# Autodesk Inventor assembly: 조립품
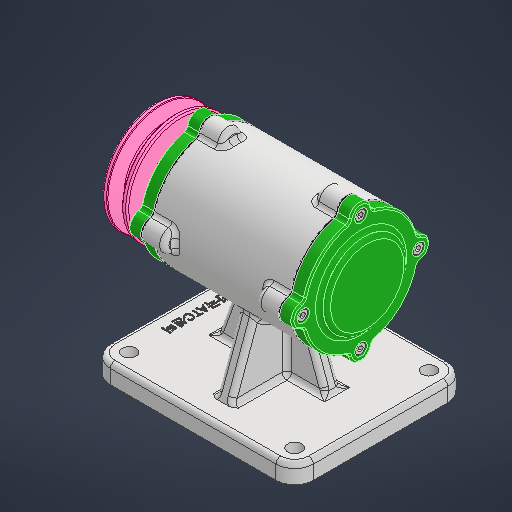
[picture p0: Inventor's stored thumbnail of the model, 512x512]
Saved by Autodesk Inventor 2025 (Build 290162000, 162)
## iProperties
Created: 2025-08
Part Number: 조립품
Document SubType Name: Assembly
Designer: infra006
Author: infra006
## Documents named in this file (12)
- C:\Users\infra006\Desktop\750806V1011\조립품.iam
- C:\Users\infra006\Desktop\750806V1011\부품eh.ipt
- C:\Users\infra006\Desktop\시험5\공용부품_20250517_2 (3)\앞커버\앞커버.ipt
- C:\Users\infra006\Desktop\시험5\공용부품_20250517_2 (3)\오일 실\오일 실.ipt
- C:\Users\infra006\Desktop\시험5\공용부품_20250517_2 (3)\축\축.ipt
- C:\Users\infra006\Desktop\시험5\공용부품_20250517_2 (3)\키 4 x 4\키 4 x 4.ipt
- C:\Users\infra006\Desktop\시험5\공용부품_20250517_2 (3)\V-벨트풀리\V-벨트풀리.ipt
- C:\Users\infra006\Desktop\시험5\공용부품_20250517_2 (3)\개스킷\개스킷.ipt
- C:\Users\infra006\Desktop\시험5\공용부품_20250517_2 (3)\너트 M12 x 1.25\너트 M12 x 1.25.ipt
- C:\Users\infra006\Desktop\시험5\공용부품_20250517_2 (3)\뒤커버\뒤커버.ipt
- C:\Users\infra006\Desktop\시험5\공용부품_20250517_2 (3)\베어링 6204\베어링 6204.ipt
- C:\Users\infra006\Desktop\시험5\공용부품_20250517_2 (3)\볼트 M4 x 12\볼트 M4 x 12.ipt
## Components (3 placed, 2 different names)
1. V-벨트풀리:1
2. 개스킷:1
3. 개스킷:2
